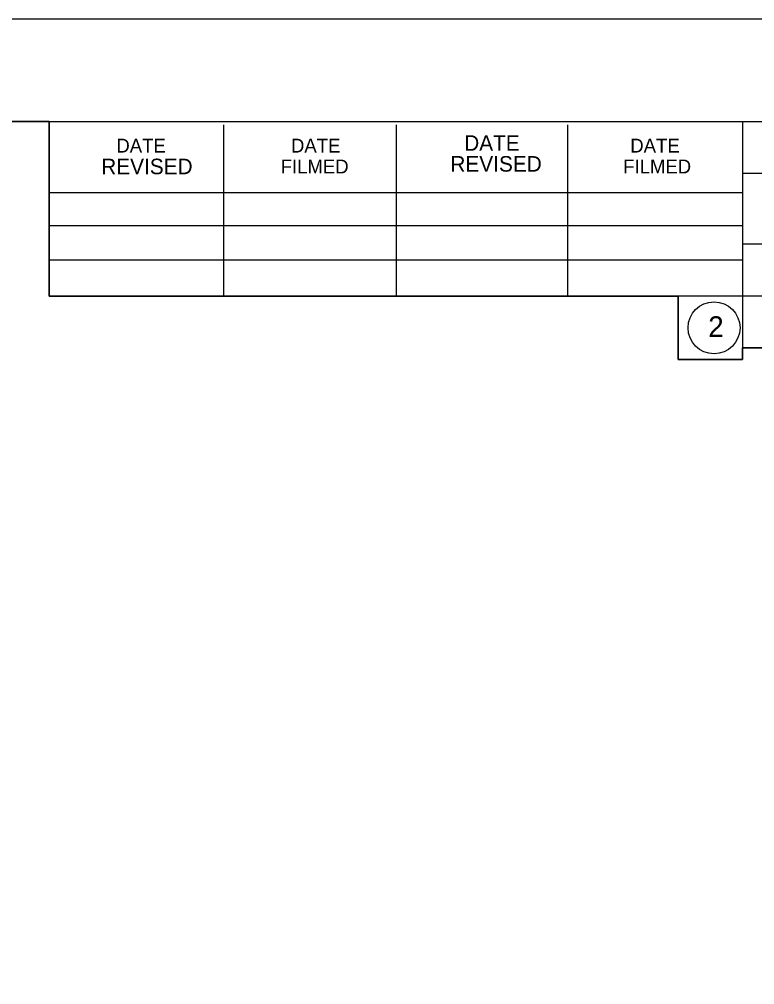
# Model space of a CAD drawing. Extents: x 0 to 1228740, y 0 to 152440.
# Drawn here: x 25.03 to 29.18, y 16.55 to 22 of the extents above; entities that cross this region are included whole.
import ezdxf

# ---------------------------------------------------------------- set-up
doc = ezdxf.new("R2010")
doc.units = 0
doc.layers.add('R_Border', color=7, linetype='Continuous')
doc.layers.add('R_No Plot', color=7, linetype='Continuous')

msp = doc.modelspace()

# ---------------------------------------------------------------- linework, layer by layer
at = {"layer": 'R_Border'}
for p, q in [((1.516, 21.4232), (33.4231, 21.4232)), ((25.1971, 20.4352), (25.1971, 21.4232)), ((26.1831, 20.4352), (26.1831, 21.4032)), ((27.1591, 20.4352), (27.1591, 21.4032)), ((28.1271, 20.4352), (28.1271, 21.4032)), ((29.1131, 21.4232), (29.1131, 20.1432)), ((33.4231, 21.1292), (29.1131, 21.1292)), ((25.1971, 21.0212), (29.1131, 21.0212)), ((25.1971, 20.8352), (29.1131, 20.8352)), ((33.4231, 20.7292), (29.1131, 20.7292)), ((25.1971, 20.4352), (25.1971, 20.6412)), ((25.1971, 20.6412), (29.1131, 20.6412)), ((33.4231, 20.4352), (25.1971, 20.4352)), ((29.1131, 20.1432), (33.4231, 20.1432))]:
    msp.add_line(p, q, dxfattribs=at)
msp.add_lwpolyline([(33.9999, 22), (0, 22), (0, 0), (33.9999, 0)], close=True, dxfattribs=at)
msp.add_circle((28.9518, 20.2569), 0.1467, dxfattribs=at)
at = {"layer": 'R_No Plot'}
msp.add_lwpolyline([(33.4231, 17.4052), (33.4231, 10.8708), (1.516, 10.8708), (1.516, 21.4232), (25.1971, 21.4232), (25.1971, 20.4352), (28.7491, 20.4352), (28.7491, 20.0782), (29.1131, 20.0782), (29.1131, 20.1432), (30.6665, 20.1432)], dxfattribs=at)
for points in [[(1.516, 21.4232), (1.516, 0.5768), (33.4231, 0.5768), (33.4231, 17.4052), (30.6665, 17.4052), (30.6665, 20.1432), (29.1131, 20.1432), (29.1131, 20.0782), (28.7491, 20.0782), (28.7491, 20.4352), (25.1971, 20.4352), (25.1971, 21.4232)], [(1.516, 21.4232), (25.1971, 21.4232), (25.1971, 20.4352), (28.7491, 20.4352), (28.7491, 20.0782), (29.1131, 20.0782), (29.1131, 20.1432), (30.6665, 20.1432), (30.6665, 17.4052), (33.4231, 17.4052), (33.4231, 0.5768), (1.516, 0.5768)]]:
    msp.add_lwpolyline(points, close=True, dxfattribs=at)

# ---------------------------------------------------------------- texts
at = {"layer": 'R_Border'}
for s, height, p in [('DATE', 0.08792, (27.5409, 21.2572)), ('DATE', 0.07819, (25.5769, 21.2472)), ('DATE', 0.07819, (26.5629, 21.2472)), ('DATE', 0.07819, (28.4789, 21.2472)), ('REVISED', 0.08792, (27.4629, 21.1392)), ('REVISED', 0.08792, (25.4912, 21.1245)), ('FILMED', 0.07819, (26.5049, 21.1292)), ('FILMED', 0.07819, (28.4389, 21.1292)), ('2', 0.1172, (28.9189, 20.2049))]:
    msp.add_text(s, height=height, dxfattribs=at).set_placement(p)

doc.saveas('drawing.dxf')
